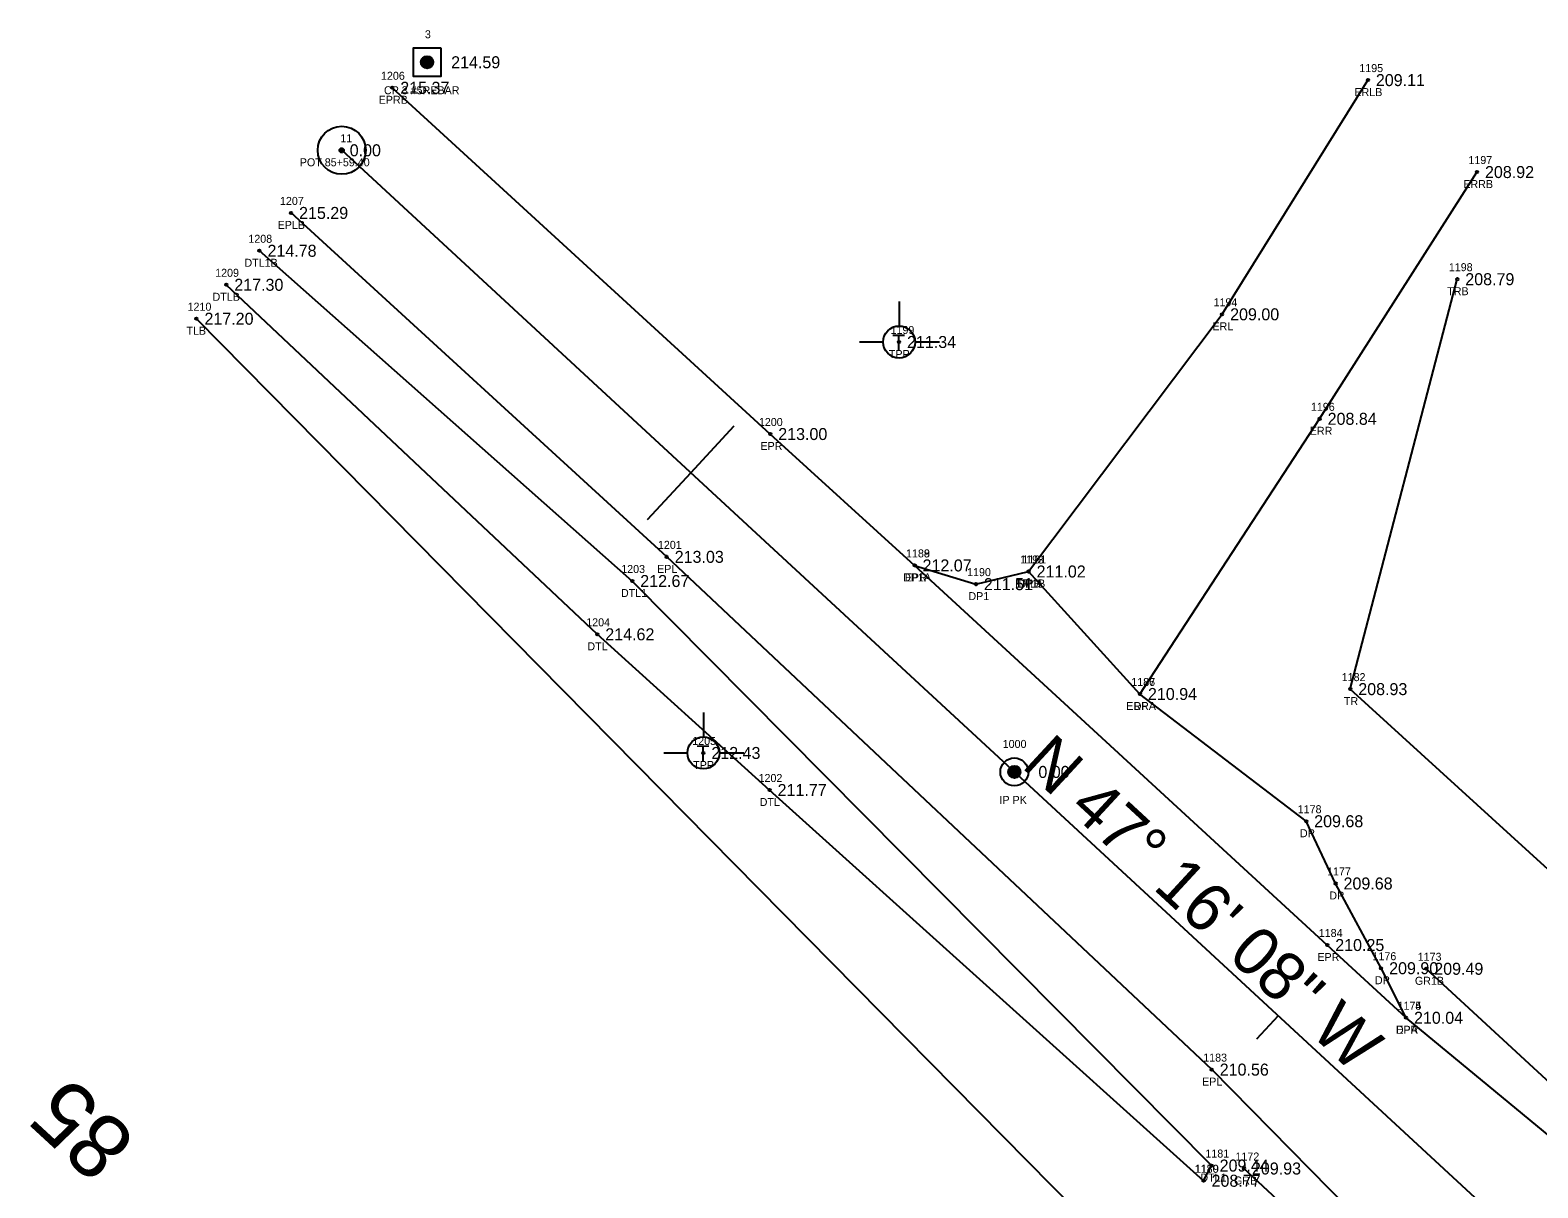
# Model space of a CAD drawing. Extents: x 2259948 to 2261336, y 1064647 to 1065986.
# Drawn here: x 2260236.5 to 2260425, y 1065419.1 to 1065563.8 of the extents above; entities that cross this region are included whole.
import ezdxf

# ---------------------------------------------------------------- set-up
doc = ezdxf.new("R2010")
doc.units = 0
for name, color, linetype in [('RD_EX_Driveway', 7, 'Continuous'), ('RD_EX_Driveway_txCode', 7, 'Continuous'), ('RD_EX_DV_Prop_txCode', 7, 'Continuous'), ('RD_EX_DV_PropPin', 7, 'Continuous'), ('RD_EX_GuardRail', 7, 'Continuous'), ('RD_EX_GuardRail_txCode', 7, 'Continuous'), ('RD_EX_H2O', 7, 'Continuous'), ('RD_EX_H2O_txCode', 7, 'Continuous'), ('RD_EX_Road', 7, 'Continuous'), ('RD_EX_Road_txCode', 7, 'Continuous'), ('RD_EX_TX_Driveway_ELEV', 7, 'Continuous'), ('RD_EX_TX_DV_Prop_ELEV', 7, 'Continuous'), ('RD_EX_TX_GuardRail_ELEV', 7, 'Continuous'), ('RD_EX_TX_H2O_ELEV', 7, 'Continuous'), ('RD_EX_TX_Road_ELEV', 7, 'Continuous'), ('RD_EX_TX_UT_ELEV', 7, 'Continuous'), ('RD_EX_TX_VEG_ELEV', 7, 'Continuous'), ('RD_EX_UT', 7, 'Continuous'), ('RD_EX_UT_txCode', 7, 'Continuous'), ('RD_EX_VEG', 7, 'Continuous'), ('RD_EX_VEG_txCode', 7, 'Continuous'), ('RD_HC_Cl', 7, 'Continuous'), ('RD_HC_Data', 7, 'Continuous'), ('RD_HC_Data_Tic', 7, 'Continuous'), ('RD_HC_Survey', 7, 'Continuous'), ('RD_HC_Survey_ELEV', 7, 'Continuous'), ('RD_HC_Survey_txCode', 7, 'Continuous'), ('RD_HC_TX_Sta50', 7, 'Continuous'), ('RD_HC_txCode', 7, 'Continuous'), ('RD_SMD_Locator', 7, 'Continuous')]:
    doc.layers.add(name, color=color, linetype=linetype)

msp = doc.modelspace()

# ---------------------------------------------------------------- linework, layer by layer
at = {"layer": 'RD_EX_Driveway'}
for points in [[(2260347.1, 1065496.93), (2260354.77, 1065494.59), (2260361.36, 1065496.17)], [(2260408.54, 1065440.4), (2260405.43, 1065446.59), (2260399.73, 1065457.18), (2260396.06, 1065464.96), (2260375.28, 1065480.86), (2260361.36, 1065496.17)]]:
    msp.add_lwpolyline(points, dxfattribs=at)
at = {"layer": 'RD_EX_DV_PropPin'}
for p, q in [((2260358.85, 1065470.93), (2260358.85, 1065471.32)), ((2260358.88, 1065470.83), (2260358.88, 1065471.42)), ((2260358.92, 1065470.75), (2260358.92, 1065471.49)), ((2260358.95, 1065470.7), (2260358.95, 1065471.55)), ((2260358.99, 1065470.65), (2260358.99, 1065471.6)), ((2260359.02, 1065470.61), (2260359.02, 1065471.64)), ((2260359.06, 1065470.57), (2260359.06, 1065471.67)), ((2260359.09, 1065470.54), (2260359.09, 1065471.71)), ((2260359.13, 1065470.51), (2260359.13, 1065471.73)), ((2260359.16, 1065470.49), (2260359.16, 1065471.76)), ((2260359.2, 1065470.47), (2260359.2, 1065471.78)), ((2260359.23, 1065470.45), (2260359.23, 1065471.8)), ((2260359.27, 1065470.43), (2260359.27, 1065471.82)), ((2260359.3, 1065470.42), (2260359.3, 1065471.83)), ((2260359.34, 1065470.4), (2260359.34, 1065471.84)), ((2260359.37, 1065470.39), (2260359.37, 1065471.86)), ((2260359.41, 1065470.38), (2260359.41, 1065471.86)), ((2260359.44, 1065470.38), (2260359.44, 1065471.87)), ((2260359.48, 1065470.37), (2260359.48, 1065471.88)), ((2260359.51, 1065470.37), (2260359.51, 1065471.88)), ((2260359.55, 1065470.36), (2260359.55, 1065471.88)), ((2260359.58, 1065470.36), (2260359.58, 1065471.89)), ((2260359.62, 1065470.36), (2260359.62, 1065471.88)), ((2260359.65, 1065470.37), (2260359.65, 1065471.88)), ((2260359.69, 1065470.37), (2260359.69, 1065471.88)), ((2260359.72, 1065470.38), (2260359.72, 1065471.87)), ((2260359.76, 1065470.38), (2260359.76, 1065471.86)), ((2260359.79, 1065470.39), (2260359.79, 1065471.86)), ((2260359.83, 1065470.4), (2260359.83, 1065471.84)), ((2260359.86, 1065470.42), (2260359.86, 1065471.83)), ((2260359.9, 1065470.43), (2260359.9, 1065471.82)), ((2260359.93, 1065470.45), (2260359.93, 1065471.8)), ((2260359.97, 1065470.47), (2260359.97, 1065471.78)), ((2260360, 1065470.49), (2260360, 1065471.76)), ((2260360.04, 1065470.51), (2260360.04, 1065471.73)), ((2260360.07, 1065470.54), (2260360.07, 1065471.71)), ((2260360.11, 1065470.57), (2260360.11, 1065471.67)), ((2260360.14, 1065470.61), (2260360.14, 1065471.64)), ((2260360.18, 1065470.65), (2260360.18, 1065471.6)), ((2260360.21, 1065470.7), (2260360.21, 1065471.55)), ((2260360.25, 1065470.75), (2260360.25, 1065471.49)), ((2260360.28, 1065470.83), (2260360.28, 1065471.42)), ((2260360.32, 1065470.93), (2260360.32, 1065471.32))]:
    msp.add_line(p, q, dxfattribs=at)
for radius in [1.75, 0.761]:
    msp.add_circle((2260359.58, 1065471.12), radius, dxfattribs=at)
at = {"layer": 'RD_EX_GuardRail'}
for p, q in [((2260473.16, 1065389.12), (2260411.07, 1065446.52)), ((2260450.57, 1065363.73), (2260388.28, 1065421.56))]:
    msp.add_line(p, q, dxfattribs=at)
at = {"layer": 'RD_EX_H2O'}
for points in [[(2260383.23, 1065420.03), (2260384.24, 1065421.93), (2260311.81, 1065494.98), (2260265.21, 1065536.25)], [(2260383.23, 1065420.03), (2260328.98, 1065468.86), (2260307.44, 1065488.32), (2260261.06, 1065532)]]:
    msp.add_lwpolyline(points, dxfattribs=at)
at = {"layer": 'RD_EX_Road'}
for points in [[(2260361.36, 1065496.17), (2260385.55, 1065528.31), (2260403.77, 1065557.58)], [(2260471.29, 1065388.66), (2260408.54, 1065440.4), (2260398.69, 1065449.49), (2260347.1, 1065496.93), (2260329.06, 1065513.35), (2260281.81, 1065556.62)], [(2260375.28, 1065480.86), (2260397.74, 1065515.25), (2260417.41, 1065546.09)], [(2260450.76, 1065366.34), (2260384.25, 1065433.92), (2260316.12, 1065498), (2260269.16, 1065540.98)]]:
    msp.add_lwpolyline(points, dxfattribs=at)
at = {"layer": 'RD_EX_UT'}
for p, q in [((2260345.16, 1065529.92), (2260345.16, 1065526.85)), ((2260340.23, 1065524.86), (2260343.16, 1065524.86)), ((2260347.16, 1065524.86), (2260350.23, 1065524.86)), ((2260320.7, 1065478.56), (2260320.7, 1065475.49)), ((2260315.77, 1065473.51), (2260318.7, 1065473.51)), ((2260322.7, 1065473.51), (2260325.77, 1065473.51))]:
    msp.add_line(p, q, dxfattribs=at)
for centre in [(2260345.16, 1065524.85), (2260320.7, 1065473.49)]:
    msp.add_circle(centre, 2, dxfattribs=at)
at = {"layer": 'RD_EX_VEG'}
for points in [[(2261134.31, 1064842.95), (2260842.2, 1065097.67), (2260806.91, 1065126.77), (2260758.4, 1065156.57), (2260401.57, 1065481.47), (2260414.95, 1065532.7)], [(2261105.29, 1064796.67), (2260883, 1064984.96), (2260766.14, 1065062.68), (2260367.33, 1065416.28), (2260257.33, 1065527.76)]]:
    msp.add_lwpolyline(points, dxfattribs=at)
at = {"layer": 'RD_HC_Cl'}
msp.add_line((2260486.9, 1065353.51), (2260275.49, 1065548.81), dxfattribs=at)
at = {"layer": 'RD_HC_Data'}
for radius in [3, 0.282]:
    msp.add_circle((2260275.49, 1065548.81), radius, dxfattribs=at)
at = {"layer": 'RD_HC_Data_Tic'}
for p, q in [((2260319.12, 1065508.5), (2260324.55, 1065514.38)), ((2260319.12, 1065508.5), (2260313.69, 1065502.63)), ((2260392.57, 1065440.65), (2260389.86, 1065437.71))]:
    msp.add_line(p, q, dxfattribs=at)
at = {"layer": 'RD_HC_Survey'}
for p, q in [((2260286.01, 1065559.05), (2260286.01, 1065560.56)), ((2260286.04, 1065559.05), (2260286.04, 1065560.57)), ((2260286.06, 1065559.04), (2260286.06, 1065560.57)), ((2260286.09, 1065559.04), (2260286.09, 1065560.57)), ((2260286.11, 1065559.04), (2260286.11, 1065560.57)), ((2260286.14, 1065559.04), (2260286.14, 1065560.58)), ((2260286.16, 1065559.04), (2260286.16, 1065560.58)), ((2260286.19, 1065559.04), (2260286.19, 1065560.58)), ((2260286.21, 1065559.04), (2260286.21, 1065560.57)), ((2260286.24, 1065559.04), (2260286.24, 1065560.57)), ((2260286.26, 1065559.04), (2260286.26, 1065560.57)), ((2260286.29, 1065559.05), (2260286.29, 1065560.57)), ((2260286.31, 1065559.05), (2260286.31, 1065560.56)), ((2260286.34, 1065559.06), (2260286.34, 1065560.56)), ((2260285.42, 1065559.63), (2260285.42, 1065559.99)), ((2260285.44, 1065559.54), (2260285.44, 1065560.07)), ((2260285.47, 1065559.48), (2260285.47, 1065560.13)), ((2260285.49, 1065559.44), (2260285.49, 1065560.18)), ((2260285.52, 1065559.39), (2260285.52, 1065560.22)), ((2260285.54, 1065559.36), (2260285.54, 1065560.26)), ((2260285.57, 1065559.32), (2260285.57, 1065560.29)), ((2260285.59, 1065559.3), (2260285.59, 1065560.32)), ((2260285.62, 1065559.27), (2260285.62, 1065560.34)), ((2260285.64, 1065559.24), (2260285.64, 1065560.37)), ((2260285.67, 1065559.22), (2260285.67, 1065560.39)), ((2260285.69, 1065559.2), (2260285.69, 1065560.41)), ((2260285.72, 1065559.18), (2260285.72, 1065560.43)), ((2260285.74, 1065559.17), (2260285.74, 1065560.45)), ((2260285.77, 1065559.15), (2260285.77, 1065560.46)), ((2260285.79, 1065559.14), (2260285.79, 1065560.48)), ((2260285.82, 1065559.12), (2260285.82, 1065560.49)), ((2260285.84, 1065559.11), (2260285.84, 1065560.5)), ((2260285.87, 1065559.1), (2260285.87, 1065560.51)), ((2260285.89, 1065559.09), (2260285.89, 1065560.52)), ((2260285.92, 1065559.08), (2260285.92, 1065560.53)), ((2260285.94, 1065559.07), (2260285.94, 1065560.54)), ((2260285.96, 1065559.06), (2260285.96, 1065560.55)), ((2260285.99, 1065559.06), (2260285.99, 1065560.55)), ((2260286.36, 1065559.06), (2260286.36, 1065560.55)), ((2260286.39, 1065559.07), (2260286.39, 1065560.54)), ((2260286.41, 1065559.08), (2260286.41, 1065560.54)), ((2260286.43, 1065559.08), (2260286.43, 1065560.53)), ((2260286.46, 1065559.09), (2260286.46, 1065560.52)), ((2260286.48, 1065559.1), (2260286.48, 1065560.51)), ((2260286.51, 1065559.12), (2260286.51, 1065560.5)), ((2260286.53, 1065559.13), (2260286.53, 1065560.48)), ((2260286.56, 1065559.14), (2260286.56, 1065560.47)), ((2260286.58, 1065559.16), (2260286.58, 1065560.45)), ((2260286.61, 1065559.18), (2260286.61, 1065560.44)), ((2260286.63, 1065559.19), (2260286.63, 1065560.42)), ((2260286.66, 1065559.21), (2260286.66, 1065560.4)), ((2260286.68, 1065559.23), (2260286.68, 1065560.38)), ((2260286.71, 1065559.26), (2260286.71, 1065560.36)), ((2260286.73, 1065559.28), (2260286.73, 1065560.33)), ((2260286.76, 1065559.31), (2260286.76, 1065560.3)), ((2260286.78, 1065559.34), (2260286.78, 1065560.27)), ((2260286.81, 1065559.38), (2260286.81, 1065560.24)), ((2260286.83, 1065559.41), (2260286.83, 1065560.2)), ((2260286.86, 1065559.46), (2260286.86, 1065560.15)), ((2260286.88, 1065559.51), (2260286.88, 1065560.1)), ((2260286.91, 1065559.58), (2260286.91, 1065560.03)), ((2260286.93, 1065559.69), (2260286.93, 1065559.92))]:
    msp.add_line(p, q, dxfattribs=at)
msp.add_lwpolyline([(2260287.92, 1065561.56), (2260284.42, 1065561.56), (2260284.42, 1065558.06), (2260287.92, 1065558.06)], close=True, dxfattribs=at)
msp.add_circle((2260286.17, 1065559.81), 0.769, dxfattribs=at)
at = {"layer": 'RD_SMD_Locator'}
for centre in [(2260286.17, 1065559.81), (2260403.77, 1065557.58), (2260281.81, 1065556.62), (2260275.49, 1065548.81), (2260417.41, 1065546.09), (2260269.16, 1065540.98), (2260265.21, 1065536.25), (2260414.95, 1065532.7), (2260261.06, 1065532), (2260257.33, 1065527.76), (2260385.55, 1065528.31), (2260345.16, 1065524.85), (2260397.74, 1065515.25), (2260329.06, 1065513.35), (2260316.12, 1065498), (2260347.1, 1065496.93), (2260347.1, 1065496.93), (2260311.81, 1065494.98), (2260354.77, 1065494.59), (2260361.36, 1065496.17), (2260361.36, 1065496.17), (2260361.36, 1065496.17), (2260307.44, 1065488.32), (2260401.57, 1065481.47), (2260375.28, 1065480.86), (2260375.28, 1065480.86), (2260320.7, 1065473.49), (2260359.58, 1065471.12), (2260328.98, 1065468.86), (2260396.06, 1065464.96), (2260399.73, 1065457.18), (2260398.69, 1065449.49), (2260405.43, 1065446.59), (2260411.07, 1065446.52), (2260408.54, 1065440.4), (2260408.54, 1065440.4), (2260384.25, 1065433.92), (2260384.24, 1065421.93), (2260388.28, 1065421.56), (2260383.23, 1065420.03), (2260383.23, 1065420.03)]:
    msp.add_circle(centre, 0.15, dxfattribs=at)

# ---------------------------------------------------------------- texts
at = {"layer": 'RD_EX_Driveway_txCode'}
for s, p in [('1189', (2260346.04, 1065497.93)), ('1190', (2260353.67, 1065495.59)), ('1192', (2260360.3, 1065497.17)), ('1191', (2260360.58, 1065497.17)), ('DP1A', (2260345.67, 1065494.93)), ('DP1B', (2260359.94, 1065494.17)), ('DPB', (2260360.11, 1065494.17)), ('DP1', (2260353.83, 1065492.59)), ('1186', (2260374.19, 1065481.86)), ('DP', (2260374.5, 1065478.86)), ('1178', (2260395, 1065465.96)), ('DP', (2260395.28, 1065462.96)), ('1177', (2260398.67, 1065458.18)), ('DP', (2260398.95, 1065455.18)), ('1176', (2260404.35, 1065447.59)), ('DP', (2260404.65, 1065444.59)), ('1175', (2260407.48, 1065441.4)), ('DPA', (2260407.27, 1065438.4))]:
    msp.add_text(s, height=1, dxfattribs=at).set_placement(p)
at = {"layer": 'RD_EX_DV_Prop_txCode'}
for s, p in [('1000', (2260358.12, 1065474.12)), ('IP PK', (2260357.72, 1065467.12))]:
    msp.add_text(s, height=1, dxfattribs=at).set_placement(p)
at = {"layer": 'RD_EX_GuardRail_txCode'}
for s, p in [('1173', (2260410, 1065447.52)), ('GR1B', (2260409.65, 1065444.52)), ('1172', (2260387.22, 1065422.56)), ('GRB', (2260387.03, 1065419.56))]:
    msp.add_text(s, height=1, dxfattribs=at).set_placement(p)
at = {"layer": 'RD_EX_H2O_txCode'}
for s, p in [('1208', (2260263.82, 1065537.25)), ('DTL1B', (2260263.33, 1065534.25)), ('1209', (2260259.67, 1065533)), ('DTLB', (2260259.34, 1065530)), ('1203', (2260310.43, 1065495.98)), ('DTL1', (2260310.4, 1065492.98)), ('1204', (2260306.06, 1065489.32)), ('DTL', (2260306.2, 1065486.32)), ('1202', (2260327.6, 1065469.86)), ('DTL', (2260327.74, 1065466.86)), ('1181', (2260383.46, 1065422.93)), ('1180', (2260382.13, 1065421.03)), ('1179', (2260382.17, 1065421.03)), ('DTL1', (2260382.83, 1065419.93))]:
    msp.add_text(s, height=1, dxfattribs=at).set_placement(p)
at = {"layer": 'RD_EX_Road_txCode'}
for s, p in [('1195', (2260402.7, 1065558.58)), ('1206', (2260280.4, 1065557.62)), ('EPRB', (2260280.11, 1065554.62)), ('ERLB', (2260402.09, 1065555.58)), ('1197', (2260416.34, 1065547.09)), ('ERRB', (2260415.7, 1065544.09)), ('1207', (2260267.77, 1065541.98)), ('EPLB', (2260267.48, 1065538.98)), ('1194', (2260384.48, 1065529.31)), ('ERL', (2260384.34, 1065526.31)), ('1196', (2260396.65, 1065516.25)), ('1200', (2260327.64, 1065514.35)), ('ERR', (2260396.51, 1065513.25)), ('EPR', (2260327.84, 1065511.35)), ('1201', (2260315.02, 1065499)), ('1188', (2260346.04, 1065497.93)), ('EPL', (2260314.92, 1065496)), ('1193', (2260360.3, 1065497.17)), ('EPR', (2260345.87, 1065494.93)), ('ERLA', (2260359.67, 1065494.17)), ('1187', (2260374.21, 1065481.86)), ('ERRA', (2260373.56, 1065478.86)), ('1184', (2260397.63, 1065450.49)), ('EPR', (2260397.46, 1065447.49)), ('1174', (2260407.48, 1065441.4)), ('EPR', (2260407.31, 1065438.4)), ('1183', (2260383.19, 1065434.92)), ('EPL', (2260383.05, 1065431.92))]:
    msp.add_text(s, height=1, dxfattribs=at).set_placement(p)
at = {"layer": 'RD_EX_TX_Driveway_ELEV'}
for s, p in [('212.07', (2260348.1, 1065496.18)), ('211.02', (2260362.36, 1065495.42)), ('211.02', (2260362.36, 1065495.42)), ('211.51', (2260355.77, 1065493.84)), ('210.94', (2260376.28, 1065480.11)), ('209.68', (2260397.06, 1065464.21)), ('209.68', (2260400.73, 1065456.43)), ('209.90', (2260406.43, 1065445.84)), ('210.04', (2260409.54, 1065439.65))]:
    msp.add_text(s, height=1.5, dxfattribs=at).set_placement(p)
at = {"layer": 'RD_EX_TX_DV_Prop_ELEV'}
msp.add_text('0.00', height=1.5, dxfattribs=at).set_placement((2260362.58, 1065470.37))
at = {"layer": 'RD_EX_TX_GuardRail_ELEV'}
for s, p in [('209.49', (2260412.07, 1065445.77)), ('209.93', (2260389.28, 1065420.81))]:
    msp.add_text(s, height=1.5, dxfattribs=at).set_placement(p)
at = {"layer": 'RD_EX_TX_H2O_ELEV'}
for s, p in [('214.78', (2260266.21, 1065535.5)), ('217.30', (2260262.06, 1065531.25)), ('212.67', (2260312.81, 1065494.23)), ('214.62', (2260308.44, 1065487.57)), ('211.77', (2260329.98, 1065468.11)), ('209.44', (2260385.24, 1065421.18)), ('208.77', (2260384.23, 1065419.28)), ('208.77', (2260384.23, 1065419.28))]:
    msp.add_text(s, height=1.5, dxfattribs=at).set_placement(p)
at = {"layer": 'RD_EX_TX_Road_ELEV'}
for s, p in [('215.37', (2260282.81, 1065555.87)), ('209.11', (2260404.77, 1065556.83)), ('208.92', (2260418.41, 1065545.34)), ('215.29', (2260270.16, 1065540.23)), ('209.00', (2260386.55, 1065527.56)), ('208.84', (2260398.74, 1065514.5)), ('213.00', (2260330.06, 1065512.6)), ('213.03', (2260317.12, 1065497.25)), ('212.07', (2260348.1, 1065496.18)), ('211.02', (2260362.36, 1065495.42)), ('210.94', (2260376.28, 1065480.11)), ('210.25', (2260399.69, 1065448.74)), ('210.04', (2260409.54, 1065439.65)), ('210.56', (2260385.25, 1065433.17))]:
    msp.add_text(s, height=1.5, dxfattribs=at).set_placement(p)
at = {"layer": 'RD_EX_TX_UT_ELEV'}
for s, p in [('211.34', (2260346.16, 1065524.1)), ('212.43', (2260321.7, 1065472.74))]:
    msp.add_text(s, height=1.5, dxfattribs=at).set_placement(p)
at = {"layer": 'RD_EX_TX_VEG_ELEV'}
for s, p in [('208.79', (2260415.95, 1065531.95)), ('217.20', (2260258.33, 1065527.01)), ('208.93', (2260402.57, 1065480.72))]:
    msp.add_text(s, height=1.5, dxfattribs=at).set_placement(p)
at = {"layer": 'RD_EX_UT'}
for p in [(2260344.31, 1065523.8), (2260319.85, 1065472.45)]:
    msp.add_text('T', height=2, dxfattribs=at).set_placement(p)
at = {"layer": 'RD_EX_UT_txCode'}
for s, p in [('1199', (2260344.1, 1065525.85)), ('TPP', (2260343.89, 1065522.85)), ('1205', (2260319.31, 1065474.49)), ('TPP', (2260319.43, 1065471.49))]:
    msp.add_text(s, height=1, dxfattribs=at).set_placement(p)
at = {"layer": 'RD_EX_VEG_txCode'}
for s, p in [('1198', (2260413.89, 1065533.7)), ('TRB', (2260413.69, 1065530.7)), ('1210', (2260256.22, 1065528.76)), ('TLB', (2260256.08, 1065525.76)), ('1182', (2260400.5, 1065482.47)), ('TR', (2260400.77, 1065479.47))]:
    msp.add_text(s, height=1, dxfattribs=at).set_placement(p)
at = {"layer": 'RD_HC_Data'}
msp.add_text('N 47%%d 16\' 08" W', height=6, rotation=317.2689, dxfattribs=at).set_placement((2260360.34, 1065471.79))
at = {"layer": 'RD_HC_Survey_ELEV'}
for s, p in [('214.59', (2260289.17, 1065559.06)), ('0.00', (2260276.49, 1065548.06))]:
    msp.add_text(s, height=1.5, dxfattribs=at).set_placement(p)
at = {"layer": 'RD_HC_Survey_txCode'}
for s, p in [('3', (2260285.89, 1065562.81)), ('CP 3 #5REBAR', (2260280.77, 1065555.81))]:
    msp.add_text(s, height=1, dxfattribs=at).set_placement(p)
at = {"layer": 'RD_HC_TX_Sta50'}
msp.add_text('85', height=8, rotation=137.2689, dxfattribs=at).set_placement((2260250.07, 1065425.26))
at = {"layer": 'RD_HC_txCode'}
for s, p in [('11', (2260275.32, 1065549.81)), ('POT 85+59.40', (2260270.25, 1065546.81))]:
    msp.add_text(s, height=1, dxfattribs=at).set_placement(p)

doc.saveas('drawing.dxf')
